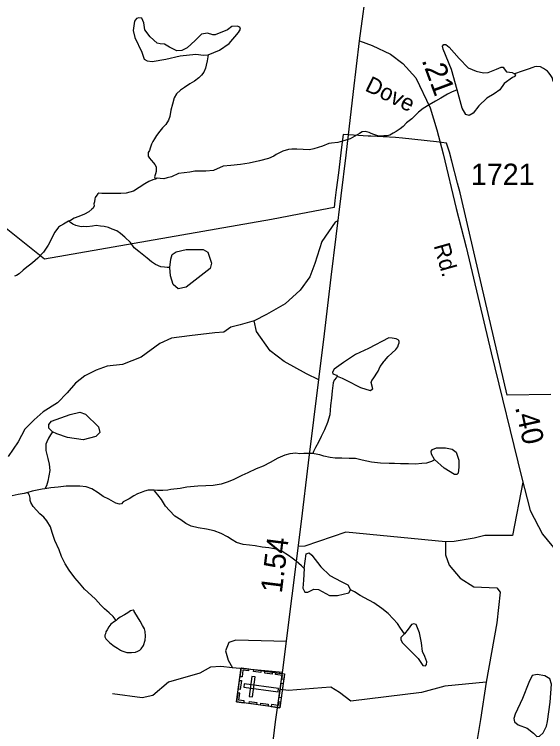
# Model space of a CAD drawing. Extents: x 2056842 to 2160602, y 826753 to 1016856.
# Drawn here: x 2090235 to 2093334, y 855779 to 859964 of the extents above; entities that cross this region are included whole.
import ezdxf

# ---------------------------------------------------------------- set-up
doc = ezdxf.new("R2010")
doc.units = 0
for name, color, linetype in [('Exist Boundary Political City Limit New', 7, 'Continuous'), ('Exist Cultural Cemetery CELL', 7, 'Continuous'), ('Exist Hydrographic Creek Single Shore', 7, 'Continuous'), ('Exist Hydrographic Misc Water Feature', 7, 'Continuous'), ('Exist Road Non-System Type 51', 7, 'Continuous'), ('Exist Road Primary NC Attributed', 7, 'Continuous'), ('Exist Road Primary NC Service Mileage Hundredths English Label', 7, 'Continuous'), ('Exist Road Secondary Mileage Hundredths English Label', 7, 'Continuous'), ('Exist Road Secondary Type 51 Attributed', 7, 'Continuous'), ('Exist Road Secondary Type 51 Label', 7, 'Continuous'), ('Exist Road Secondary Type 51 Number Label', 7, 'Continuous'), ('Map Preparation Boundary City Limit Buffer Line', 7, 'Continuous')]:
    doc.layers.add(name, color=color, linetype=linetype)

msp = doc.modelspace()

# ---------------------------------------------------------------- linework, layer by layer
at = {"layer": 'Exist Boundary Political City Limit New'}
for points in [[(2091735, 858766.5), (2090411.6, 858536.4), (2090000, 858863), (2089992.9, 858868.9), (2089910.4, 858937), (2089833.6, 859000.2), (2089688.6, 859184.9), (2089636.1, 859251.8), (2089509.2, 859414.6), (2089471.8, 859460.8), (2089211, 860000)], [(2093363.8, 857745.3), (2093110.2, 857743), (2092921.1, 858553.7), (2092835.1, 858922.4), (2092820, 858979.9), (2092786.9, 859108.1), (2092772.6, 859160.4), (2092756.2, 859212.8), (2092696.5, 859219.6), (2092500, 859242.4), (2092459.1, 859244.8), (2092314.6, 859253.1), (2092307.8, 859253.5), (2092299.6, 859254), (2092213.6, 859259), (2092152.8, 859262.9), (2092143.6, 859189.6), (2092124.9, 859039.4), (2092112.4, 858939.7), (2092104.9, 858878.8)], [(2092104.9, 858878.8), (2092099.6, 858837.5), (2091946.8, 858807.5), (2091735, 858766.5)]]:
    msp.add_lwpolyline(points, dxfattribs=at)
at = {"layer": 'Exist Cultural Cemetery CELL'}
for points in [[(2091531.8, 855953.6), (2091559, 856150.8), (2091811.3, 856115.9), (2091784, 855918.7)], [(2091602, 856144.9), (2091600.5, 856133.7), (2091568.6, 856138.1), (2091563, 856097.9), (2091552, 856099.4), (2091559.1, 856150.9)], [(2091672.8, 856123.6), (2091629.9, 856129.5), (2091631.5, 856140.8), (2091674.4, 856134.9)], [(2091738.1, 856114.5), (2091695.2, 856120.5), (2091696.8, 856131.8), (2091739.7, 856125.8)], [(2091604.8, 855984.7), (2091623.3, 855982.1), (2091639.4, 856098.8), (2091620.9, 856101.3)], [(2091806.7, 856083.1), (2091795.4, 856084.7), (2091798.4, 856106.5), (2091758.3, 856112), (2091759.9, 856123), (2091811.3, 856115.9)], [(2091541.9, 856027), (2091549, 856078.3), (2091560.3, 856076.7), (2091553.2, 856025.4)], [(2091575.7, 856057.6), (2091573.2, 856039.1), (2091774, 856011.3), (2091776.6, 856029.8)], [(2091780.5, 855977.2), (2091792.1, 856061.2), (2091803.4, 856059.7), (2091791.8, 855975.6)], [(2091574.7, 855947.6), (2091576.2, 855958.9), (2091544.3, 855963.3), (2091549.9, 856003.5), (2091538.9, 856005), (2091531.8, 855953.6)], [(2091648.1, 855937.5), (2091605.2, 855943.4), (2091606.8, 855954.7), (2091649.7, 855948.7)], [(2091714.7, 855928.2), (2091671.8, 855934.2), (2091673.4, 855945.5), (2091716.3, 855939.5)], [(2091788.5, 855951.5), (2091777.1, 855953), (2091774.1, 855931.3), (2091734.1, 855936.8), (2091732.5, 855925.8), (2091783.9, 855918.7)]]:
    msp.add_lwpolyline(points, close=True, dxfattribs=at)
at = {"layer": 'Exist Hydrographic Creek Single Shore'}
for points in [[(2091366.5, 859728.2), (2091359.2, 859693.4), (2091353.1, 859667.5), (2091349.4, 859649.4), (2091339.7, 859627.4), (2091327.2, 859609.3), (2091311.4, 859593.1), (2091285.4, 859575.1), (2091259.4, 859559.2), (2091227.8, 859536.8), (2091203.8, 859521), (2091181.6, 859500.8), (2091167.9, 859476.9), (2091157.6, 859440.7), (2091147.8, 859404.9), (2091142.3, 859368.8), (2091134.5, 859346.9), (2091118.5, 859322.5), (2091100.2, 859302.5), (2091084.6, 859282.6), (2091064.6, 859256.4), (2091052.7, 859238.4), (2091042.8, 859222.4), (2091034.4, 859206.2), (2091026.6, 859184.3), (2091022.5, 859170.3), (2091015.1, 859158.4), (2091015.1, 859148.3), (2091014.7, 859136.5), (2091022.9, 859124.3), (2091032.8, 859114.4), (2091047.1, 859098.4), (2091055.3, 859088.6), (2091061.5, 859074.3), (2091062.9, 859060.7), (2091063.1, 859046.4), (2091059, 859034.5), (2091053.5, 859016.3), (2091057.6, 859002.6)], [(2092817.1, 859522.9), (2092813.6, 859522), (2092789.4, 859511.9), (2092761.6, 859497.9), (2092723.4, 859475.7), (2092691.6, 859457.4), (2092653.9, 859435.5), (2092620.1, 859415.5), (2092592, 859393.3), (2092553.8, 859355.3), (2092522.3, 859330.9), (2092502.2, 859310.8), (2092486.4, 859297), (2092462.4, 859280.7), (2092444.1, 859270.9), (2092424.3, 859258.5), (2092410.5, 859254.5), (2092390.4, 859254.7), (2092372.4, 859252.6), (2092354.3, 859254.5), (2092332.2, 859262.3), (2092316.4, 859268.3), (2092304.1, 859274.2), (2092280.5, 859280.3), (2092264.3, 859278.2), (2092248.3, 859268.1), (2092220.4, 859254.1), (2092194.4, 859238.2), (2092162.6, 859228), (2092122.6, 859215.8), (2092084.7, 859211.8), (2092068.5, 859209.8), (2092032.6, 859195.3), (2091982.8, 859179.3), (2091956.7, 859173.2), (2091882.5, 859177), (2091854.4, 859176.8), (2091834.5, 859175), (2091800.5, 859166.8), (2091784.7, 859158.6), (2091762.8, 859146.5), (2091748.6, 859136.5), (2091716.6, 859122.7), (2091664.9, 859110.3), (2091604.7, 859096.2), (2091554.8, 859088), (2091497, 859081.7), (2091452.9, 859077.9), (2091396.9, 859053.5), (2091351.4, 859049.5), (2091323.3, 859049.2), (2091287, 859049), (2091259.4, 859043.1), (2091192.9, 859034.9), (2091151.3, 859016.8), (2091127.3, 859010.7), (2091107.2, 859004.5), (2091085.5, 859006.5), (2091069.1, 859008.6), (2091057.6, 859002.6)], [(2091057.6, 859002.6), (2091043.2, 858998.3), (2091019.4, 858988.6), (2090995.4, 858974.4), (2090929.8, 858932), (2090887.4, 858920.1), (2090855.6, 858918), (2090807.4, 858919.7), (2090771.7, 858919.8), (2090745.9, 858919.7), (2090727.9, 858921.6), (2090721.7, 858917.7), (2090715.8, 858909.6), (2090705.7, 858895.3), (2090703.9, 858887.5), (2090701.8, 858869.5), (2090699.6, 858859.3), (2090699.8, 858847.5), (2090694, 858833.4), (2090687.9, 858827.4), (2090670, 858811.4), (2090644.2, 858799.1), (2090612, 858784.9), (2090584.1, 858775), (2090562.2, 858760.8), (2090550.5, 858756.9)], [(2090550.5, 858756.9), (2090522.2, 858740.9), (2090504.3, 858730.6), (2090492, 858722.8), (2090470.5, 858692.8), (2090458.4, 858668.6), (2090448.4, 858646.6), (2090432.8, 858616.5), (2090404.9, 858576.6), (2090372.7, 858542.5), (2090340.9, 858514.4), (2090323.3, 858500.1), (2090307.3, 858488.3), (2090287.2, 858472.2), (2090263.2, 858450.3), (2090247.4, 858440.1), (2090235.1, 858435.9)], [(2091976, 857401.5), (2091952.2, 857401.4), (2091924.1, 857401.2), (2091897.9, 857399.6), (2091876.1, 857403.2), (2091842.1, 857399), (2091812.4, 857393), (2091772.4, 857374.7), (2091726.3, 857348.9), (2091686.5, 857328.6), (2091646.3, 857312.7), (2091596.5, 857288.2), (2091562.6, 857274.3), (2091512.4, 857248.2), (2091476.9, 857234.1), (2091440.8, 857223.8), (2091394.9, 857215.7), (2091352.9, 857213.6), (2091304.9, 857211.5), (2091240.9, 857205.4), (2091203, 857197.3), (2091147.2, 857191.2), (2091131, 857188.7), (2091101.1, 857186.8), (2091070.9, 857186.9), (2091051.2, 857188.7)], [(2092686.1, 857367.7), (2092680.4, 857361.7), (2092668.3, 857355.8), (2092638.1, 857345.4), (2092612.3, 857343.6), (2092574.1, 857339.3), (2092534.2, 857341.3), (2092488.2, 857341.3), (2092452.5, 857343.1), (2092420.6, 857343.1), (2092370.3, 857344.6), (2092318, 857350.4), (2092264.5, 857362.2), (2092224.1, 857372.4), (2092188.2, 857372.2), (2092146.2, 857374.1), (2092106.2, 857374.1), (2092077.9, 857377.9), (2092040.2, 857385.7), (2092016.4, 857393.8), (2091984.2, 857399.4), (2091976, 857401.5)], [(2091051.2, 857188.7), (2091043, 857188.7), (2091014.9, 857188.5), (2090994.8, 857182.6), (2090975.4, 857174.6), (2090953, 857166.2), (2090931.3, 857154.5), (2090905, 857138.2), (2090868.9, 857120.1), (2090859.3, 857108.2), (2090849.2, 857106.1), (2090827.1, 857111.9), (2090786.9, 857135.8), (2090753.1, 857151.9), (2090725, 857171.6), (2090686.8, 857195.6), (2090653.2, 857207.6), (2090616.9, 857211.5), (2090573, 857211.2), (2090537, 857211), (2090490.8, 857205), (2090447.1, 857200.7), (2090412.9, 857196.6)], [(2091926.5, 856731), (2091910, 856747.3), (2091878.2, 856773.2), (2091856.1, 856791.2), (2091834.1, 856807.1), (2091797.8, 856829.2), (2091761.9, 856842.8), (2091719.9, 856850.8), (2091679.7, 856854.8), (2091639.7, 856862.5), (2091606.1, 856866.4), (2091569.8, 856870.3), (2091531.7, 856882.1), (2091506, 856898.2), (2091477.9, 856915.8), (2091441.6, 856935.9), (2091399.8, 856950), (2091355.5, 856959.6), (2091307.5, 856967.6), (2091265.5, 856977.2), (2091235.4, 856993.2), (2091205.4, 857015.2), (2091171.2, 857037), (2091139.2, 857069), (2091117.2, 857095.1), (2091093.3, 857132.8), (2091073, 857161), (2091052.7, 857184.8), (2091051.2, 857188.7)], [(2090313.2, 857174.4), (2090293.1, 857168.5), (2090257.3, 857162.1), (2090223.2, 857154.3)], [(2091926.5, 856731), (2091938.1, 856816.5), (2091953.9, 856821.8), (2091969.7, 856808.6), (2092022.4, 856740.1), (2092075.1, 856690), (2092141, 856655.7), (2092180.5, 856634.6), (2092196.3, 856605.6)], [(2091926.5, 856731), (2091922.3, 856663.6), (2091917, 856616.1), (2091930.2, 856592.4), (2091946, 856592.4), (2091982.9, 856610.9), (2092009.2, 856608.2), (2092072.5, 856574), (2092119.9, 856574), (2092185.8, 856589.8), (2092196.3, 856605.6)], [(2092510.4, 856350), (2092487.2, 856383.1), (2092469, 856409.4), (2092444.8, 856437), (2092414.8, 856469.1), (2092379.1, 856496.9), (2092332.8, 856530.6), (2092276.6, 856560.6), (2092252.6, 856572.4), (2092218.6, 856594.6), (2092196.3, 856605.6)]]:
    msp.add_lwpolyline(points, dxfattribs=at)
at = {"layer": 'Exist Hydrographic Misc Water Feature'}
for points in [[(2091366.5, 859728.2), (2091431.5, 859754.5), (2091488.2, 859794.1), (2091543.5, 859858.7), (2091554, 859878.4), (2091550.1, 859890.3), (2091535.6, 859895.6), (2091504, 859892.9), (2091478.9, 859873.2), (2091406.5, 859844.2), (2091392, 859844.2), (2091361.7, 859854.7), (2091327.4, 859848.1), (2091289.2, 859811.2), (2091243.1, 859769), (2091212.8, 859753.2), (2091182.5, 859751.9), (2091140.4, 859773), (2091110.1, 859790.1), (2091086.3, 859791.4), (2091067.9, 859796.7), (2091027.1, 859832.3), (2090996.8, 859873.2), (2090990.2, 859914), (2090978.3, 859941.7), (2090961.2, 859944.3), (2090946.7, 859939.1), (2090936.1, 859924.6), (2090928.2, 859869.2), (2090937.5, 859828.3), (2090978.3, 859744), (2090991.5, 859703.1), (2091009.9, 859692.6), (2091038.9, 859689.9), (2091118, 859701.8), (2091202.3, 859721.6), (2091294.5, 859732.1), (2091339.3, 859726.8), (2091366.5, 859728.2)], [(2092817.1, 859522.9), (2092785.1, 859641.5), (2092737, 859761.8), (2092733.2, 859778.3), (2092740.8, 859788.4), (2092752.2, 859788.4), (2092771.2, 859773.2), (2092829.5, 859707.3), (2092882.6, 859651.6), (2092928.2, 859632.6), (2092971.3, 859623.7), (2092999.1, 859625), (2093047.2, 859644), (2093075.1, 859656.7), (2093086.5, 859655.4), (2093091.6, 859646.5), (2093105.5, 859628.8), (2093123.2, 859626.3), (2093139.7, 859625), (2093152.5, 859618)], [(2093436.3, 859516), (2093405.4, 859533.8), (2093389.2, 859553.7), (2093377.3, 859573.8), (2093371.2, 859595.4), (2093365, 859607.7), (2093355, 859621.8), (2093345.1, 859633.4), (2093320.9, 859649.2), (2093303.1, 859657.2), (2093283.2, 859659.4), (2093269.3, 859657.1), (2093259.2, 859653.3), (2093231.1, 859645), (2093197.1, 859633.1), (2093152.5, 859618)], [(2093152.5, 859618), (2093157.4, 859611), (2093153.6, 859602.2), (2093140.9, 859595.8), (2093092.8, 859560.4), (2093067.5, 859523.6), (2093034.6, 859499.6), (2092990.3, 859475.5), (2092944.7, 859431.1), (2092910.5, 859388.1), (2092887.7, 859374.1), (2092868.7, 859379.2), (2092847.2, 859415.9), (2092817.1, 859522.9)], [(2091142.9, 858487), (2091126.7, 858486.6), (2091110.9, 858488.6), (2091089.2, 858490.7), (2091059.2, 858504.5), (2091034.6, 858520.5), (2091009, 858542.2), (2090980.7, 858564.3), (2090960.4, 858580.4), (2090934.8, 858602.1), (2090912.6, 858632.3), (2090880.4, 858663.9), (2090854.4, 858685.7), (2090832.4, 858701.6), (2090806.4, 858711.7), (2090784.2, 858721.5), (2090758.2, 858725.5), (2090738.5, 858727.6), (2090712.5, 858731.6), (2090690.3, 858729.3), (2090658.1, 858725.2), (2090638, 858727), (2090624.1, 858725.1), (2090594.2, 858731.3), (2090576.3, 858740.8), (2090562.4, 858749.1), (2090550.5, 858756.9)], [(2091142.9, 858487), (2091147.6, 858536.6), (2091155.5, 858562.9), (2091179.2, 858578.8), (2091237.2, 858591.9), (2091337.3, 858591.9), (2091363.7, 858576.1), (2091384.7, 858512.8), (2091376.8, 858481.2), (2091237.2, 858373.1), (2091189.8, 858362.6), (2091160.8, 858388.9), (2091145, 858439), (2091142.9, 858487)], [(2092118.5, 857853.8), (2092146.6, 857841.8), (2092170.6, 857830.1), (2092254.3, 857787.8), (2092309.6, 857769.3), (2092325.4, 857779.9), (2092316.8, 857816.5), (2092320.9, 857828.4), (2092328.1, 857837.9), (2092357, 857882.7), (2092368.7, 857908.9), (2092382.2, 857926.6), (2092390.6, 857938.8), (2092394.7, 857942.6), (2092416, 857967), (2092436.6, 857987), (2092460.1, 858009), (2092472, 858025), (2092476.3, 858037), (2092480, 858047), (2092480, 858055.1), (2092478.2, 858061.1), (2092474.1, 858064.9), (2092462, 858070.8), (2092438, 858074.8), (2092419.9, 858076.7), (2092301.7, 858014.5), (2092225.3, 857980.3), (2092154.2, 857932.8), (2092101.5, 857893.3), (2092090.9, 857877.4), (2092093.5, 857866.9), (2092114.4, 857859.7), (2092118.5, 857853.8)], [(2092118.5, 857853.8), (2092114.6, 857845.9), (2092100.9, 857829.7), (2092094.9, 857814), (2092089, 857767.8), (2092084.9, 857723.8), (2092079.1, 857681.7), (2092075.5, 857627.9), (2092061.7, 857583.7), (2092043.7, 857539.8), (2092023.8, 857501.8), (2092010, 857467.8), (2091991.8, 857437.6), (2091980.1, 857413.4), (2091976, 857401.5)], [(2090458, 857528.9), (2090436.2, 857550.5), (2090436.2, 857571.6), (2090452, 857590.1), (2090560, 857629.6), (2090618, 857642.8), (2090649.6, 857632.2), (2090726, 857558.4), (2090733.9, 857524.2), (2090710.2, 857500.4), (2090636.4, 857482), (2090544.2, 857495.2), (2090483.6, 857516.2), (2090458, 857528.9)], [(2090458, 857528.9), (2090446.1, 857510.8), (2090433.8, 857490.8), (2090424.2, 857470.8), (2090418, 857456.7), (2090418.4, 857438.8), (2090418, 857418.9), (2090430.3, 857372.8), (2090438.3, 857338.8), (2090442.6, 857302.8), (2090436.9, 857270.8), (2090430.9, 857240.9), (2090422.9, 857212.9), (2090412.9, 857196.6)], [(2092686.1, 857367.7), (2092667.4, 857397.7), (2092666.1, 857415.5), (2092673.7, 857425.6), (2092697.8, 857434.5), (2092749.7, 857434.5), (2092788.9, 857428.1), (2092811.7, 857409.1), (2092828.2, 857363.5), (2092828.2, 857321.7), (2092824.4, 857286.2), (2092815.5, 857278.6), (2092802.9, 857278.6), (2092742.1, 857316.6), (2092686.1, 857367.7)], [(2090412.9, 857196.6), (2090396.9, 857194.5), (2090339.3, 857182.6), (2090313.2, 857174.4)], [(2090829.4, 856428.2), (2090811.3, 856450), (2090789, 856472.1), (2090761.1, 856495.8), (2090739.3, 856517.8), (2090708.8, 856551.6), (2090684.8, 856573.5), (2090645, 856609.5), (2090614.9, 856645.4), (2090588.6, 856677.3), (2090554.4, 856721.1), (2090530.6, 856757.1), (2090510.3, 856801.2), (2090496.1, 856839), (2090472, 856895.1), (2090455.8, 856940.9), (2090445.7, 856974.9), (2090425.4, 857008.8), (2090407.4, 857030.6), (2090383.6, 857050.5), (2090363.5, 857070.5), (2090345, 857092.4), (2090331.3, 857116.4), (2090327.2, 857128.4), (2090327.2, 857140.6), (2090323.1, 857156.6), (2090317.3, 857168.5), (2090313.2, 857174.4)], [(2090829.4, 856428.2), (2090819.3, 856422), (2090797.2, 856405.9), (2090785.5, 856389.8), (2090775.6, 856373.9), (2090769.5, 856361.8), (2090767.4, 856349.9), (2090763.5, 856342), (2090763.5, 856331.9), (2090769.7, 856320), (2090779.5, 856308), (2090791.8, 856298), (2090817.9, 856278.2), (2090835.9, 856266.1), (2090854, 856254.1), (2090862.2, 856250.4), (2090891.9, 856240.2), (2090917.9, 856240.3), (2090941.9, 856242.3), (2090955.7, 856248.4), (2090967.8, 856254.6), (2090975.6, 856262.4), (2090987.9, 856282.5), (2090997.5, 856312.7), (2090999.3, 856336.7), (2090997.3, 856362.6), (2090993.6, 856378.6), (2090983.4, 856398.4), (2090969.4, 856424.4), (2090953.4, 856448.4), (2090937.2, 856474.4), (2090933.1, 856480.3), (2090933.1, 856484.4), (2090927.4, 856488.5), (2090913, 856484.5), (2090897, 856472.4), (2090877.1, 856460.3), (2090853.1, 856446.1), (2090837.6, 856434.3), (2090829.4, 856428.2)], [(2092510.4, 856350), (2092490.1, 856328.4), (2092488.9, 856315.8), (2092496.5, 856299.3), (2092544.6, 856252.4), (2092591.4, 856205.6), (2092618, 856165), (2092633.2, 856162.5), (2092638.3, 856170.1), (2092640.8, 856186.5), (2092629.4, 856217), (2092616.7, 856246.1), (2092609.2, 856298), (2092597.8, 856355.1), (2092578.8, 856403.2), (2092564.8, 856408.3), (2092552.2, 856403.2), (2092531.9, 856376.6), (2092510.4, 856350)], [(2093344.5, 855838.3), (2093359.7, 855951), (2093368.5, 856056.2), (2093358.4, 856087.8), (2093329.3, 856104.3), (2093283.7, 856111.9), (2093255.8, 856105.6), (2093235.6, 856065), (2093198.9, 855972.5), (2093155.8, 855881.3), (2093148.2, 855854.7), (2093152, 855835.7), (2093173.5, 855818), (2093225.5, 855799), (2093262.2, 855769.8), (2093282.4, 855750.8), (2093298.9, 855752.1), (2093319.1, 855772.4), (2093339.4, 855811.7), (2093344.5, 855838.3)]]:
    msp.add_lwpolyline(points, dxfattribs=at)
at = {"layer": 'Exist Road Non-System Type 51'}
msp.add_line((2091800.3, 856124.8), (2091507.7, 856150.8), dxfattribs=at)
for points in [[(2092122.8, 858758.9), (2092106.9, 858751.9), (2092028, 858639.7), (2091988.6, 858510.8), (2091959.5, 858431.9), (2091901.3, 858355), (2091814.1, 858276), (2091706.1, 858213.6), (2091634.4, 858175.2)], [(2091634.4, 858175.2), (2091551.3, 858152.3), (2091497.3, 858139.8), (2091457.9, 858110.7), (2091403.9, 858106.6), (2091256.4, 858087.9), (2091152.6, 858075.4), (2091084, 858044.2), (2090973.9, 857963.2), (2090865.9, 857921.6), (2090776.6, 857911.2), (2090713.3, 857887.3), (2090646.8, 857854.1), (2090592.8, 857812.5), (2090543, 857756.4), (2090486.9, 857698.2), (2090403.8, 857644.1), (2090349.8, 857598.4), (2090295.8, 857544.4), (2090258.4, 857469.5), (2090198.2, 857384.3)], [(2092011, 857831.3), (2091939.7, 857867.6), (2091808.9, 857938.2), (2091727.9, 858000.6), (2091646.9, 858112.8), (2091634.4, 858175.2)], [(2093200.8, 857234.4), (2093140.3, 856924), (2092979.3, 856922.9), (2092917, 856908.4), (2092800.7, 856887.6), (2092750.8, 856885.5)], [(2092750.8, 856885.5), (2092169.3, 856943.7), (2091929.4, 856861.6), (2091892.6, 856859.1)], [(2092750.8, 856885.5), (2092750.8, 856810.7), (2092771.6, 856750.4), (2092836, 856673.5), (2092914.9, 856623.6), (2093049.9, 856617.4), (2093068.6, 856592.4), (2093049.9, 856413.7), (2092986.6, 856067.6)], [(2091823.1, 856305.8), (2091526.4, 856312.9), (2091487, 856298.3), (2091466.2, 856250.5), (2091482.8, 856196.5), (2091507.7, 856150.8)], [(2091507.7, 856150.8), (2091439.2, 856159.1), (2091379, 856154.9), (2091316.6, 856119.6), (2091133.9, 856067.6), (2091042.5, 855990.7), (2090980.2, 855976.2), (2090807.8, 855999)], [(2092986.6, 856067.6), (2092745.6, 856044.8), (2092610.6, 856007.4), (2092197.3, 855957.5), (2092130.8, 856007.4), (2092081, 856038.5), (2092029.1, 856034.4), (2091834.9, 856018.8), (2091785.7, 856025.4)], [(2092986.6, 856067.6), (2092953.3, 855849.4), (2092932.6, 855720.5), (2092872.3, 855647.8), (2092337.5, 855112.6), (2092283.5, 855068.9)]]:
    msp.add_lwpolyline(points, dxfattribs=at)
at = {"layer": 'Exist Road Primary NC Attributed'}
for points in [[(2092249.2, 859809.6), (2092296.7, 860169.4), (2092334.1, 860493.7), (2092387, 860929.1), (2092432.7, 861303.2), (2092455.8, 861485.8)], [(2091255.4, 851735.3), (2091310.7, 852089.3), (2091463.3, 853439.2), (2091613.9, 854639.5), (2091758.2, 855835.6), (2091801.9, 856136.9), (2091910.9, 857004.6), (2091950.4, 857347.6), (2092044.9, 858101), (2092082.2, 858431.4), (2092170.5, 859143.2), (2092214.1, 859513.2), (2092249.2, 859809.6)]]:
    msp.add_lwpolyline(points, dxfattribs=at)
at = {"layer": 'Exist Road Secondary Type 51 Attributed'}
msp.add_lwpolyline([(2092249.2, 859809.6), (2092322.9, 859782.6), (2092428.8, 859732.7), (2092501.5, 859677.7), (2092577.3, 859593.5), (2092660.9, 859419.4), (2092699.3, 859290.6), (2092735.7, 859150.3), (2092812.5, 858832.3), (2092870.7, 858605.7), (2093017.1, 857989.5), (2093192.6, 857265.2), (2093244.5, 857069.9), (2093315.1, 856930.6), (2093407.6, 856819.4), (2093492.7, 856728), (2093679.6, 856572.1), (2093968.3, 856355.9), (2094328.7, 856078.5), (2094488.6, 855951.7), (2094613.2, 855835.3), (2094737.8, 855677.4)], dxfattribs=at)
at = {"layer": 'Map Preparation Boundary City Limit Buffer Line'}
for points in [[(2091735, 858766.5), (2090411.6, 858536.4), (2090000, 858863), (2089992.9, 858868.9), (2089910.4, 858937), (2089833.6, 859000.2), (2089688.6, 859184.9), (2089636.1, 859251.8), (2089509.2, 859414.6), (2089471.8, 859460.8), (2089211, 860000)], [(2093363.8, 857745.3), (2093110.2, 857743), (2092921.1, 858553.7), (2092835.1, 858922.4), (2092820, 858979.9), (2092786.9, 859108.1), (2092772.6, 859160.4), (2092756.2, 859212.8), (2092696.5, 859219.6), (2092500, 859242.4), (2092459.1, 859244.8), (2092314.6, 859253.1), (2092307.8, 859253.5), (2092299.6, 859254), (2092213.6, 859259), (2092152.8, 859262.9), (2092143.6, 859189.6), (2092124.9, 859039.4), (2092112.4, 858939.7), (2092104.9, 858878.8)], [(2092104.9, 858878.8), (2092099.6, 858837.5), (2091946.8, 858807.5), (2091735, 858766.5)]]:
    msp.add_lwpolyline(points, dxfattribs=at)

# ---------------------------------------------------------------- texts
at = {"layer": 'Exist Road Primary NC Service Mileage Hundredths English Label'}
msp.add_text('1.54', height=125, rotation=82.8377, dxfattribs=at).set_placement((2091794.9, 856583.2))
at = {"layer": 'Exist Road Secondary Mileage Hundredths English Label'}
for s, rotation, p in [('.21', 290.3599, (2092609.6, 859696.7)), ('.40', 282.448, (2093155.2, 857672.1))]:
    msp.add_text(s, height=125, rotation=rotation, dxfattribs=at).set_placement(p)
at = {"layer": 'Exist Road Secondary Type 51 Label'}
for s, rotation, p in [('Dove', 334.024, (2092274.7, 859521.9)), ('Rd.', 285.846, (2092680.3, 858614.9))]:
    msp.add_text(s, height=95, rotation=rotation, dxfattribs=at).set_placement(p)
at = {"layer": 'Exist Road Secondary Type 51 Number Label'}
msp.add_text('1721', height=125, dxfattribs=at).set_placement((2092897.6, 858968))

doc.saveas('drawing.dxf')
